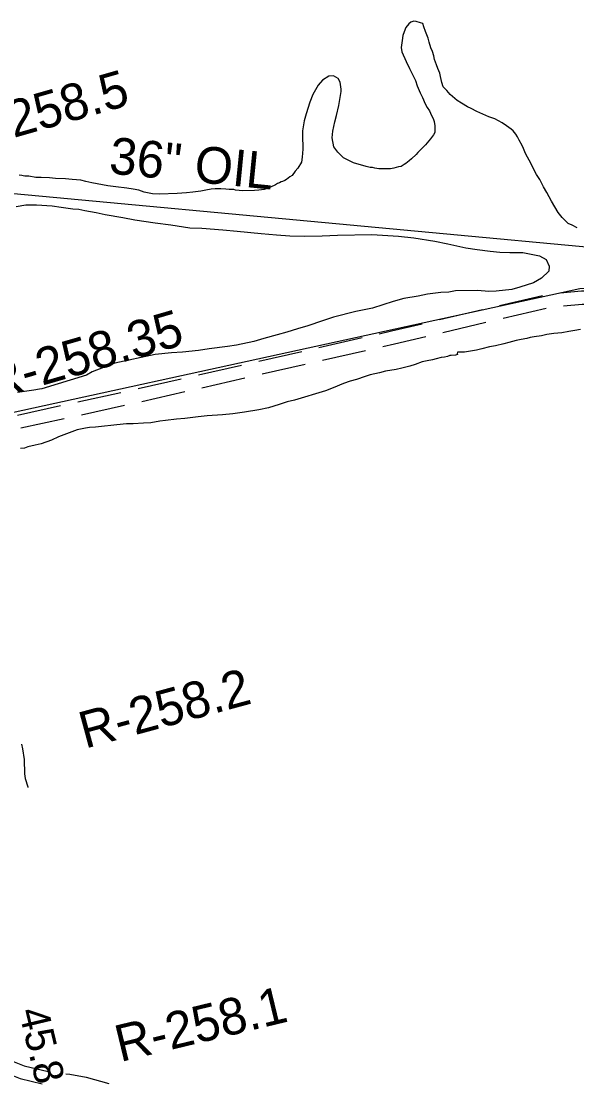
# Model space of a CAD drawing. Extents: x 3250478 to 3288318, y 788638 to 816472.
# Drawn here: x 3279198 to 3280456, y 795832 to 798238 of the extents above; entities that cross this region are included whole.
import ezdxf

# ---------------------------------------------------------------- set-up
doc = ezdxf.new("R2010")
doc.units = 0
for name, color, linetype in [('V-RIVR-RANG', 7, 'Continuous'), ('V-RIVR-RANG-IDEN', 7, 'Continuous'), ('V-ROAD-CNTR', 7, 'Continuous'), ('V-SITE-VEGE', 7, 'Continuous'), ('V-UTIL-IDEN', 7, 'Continuous'), ('V-UTIL-LINE', 7, 'Continuous')]:
    doc.layers.add(name, color=color, linetype=linetype)

msp = doc.modelspace()

# ---------------------------------------------------------------- linework, layer by layer
at = {"layer": 'V-ROAD-CNTR'}
for p, q in [((3280281.4, 797594.3), (3280378.7, 797617.2)), ((3280145.1, 797562.2), (3280242.4, 797585.1)), ((3280289.3, 797565.3), (3280386.6, 797588.2)), ((3280153, 797533.2), (3280250.4, 797556.2)), ((3279872.3, 797499.2), (3279969.8, 797521.4)), ((3279735.8, 797468.1), (3279833.3, 797490.3)), ((3279880.2, 797470.3), (3279977.7, 797492.5)), ((3279599.3, 797437), (3279696.8, 797459.2)), ((3279743.7, 797439.2), (3279841.2, 797461.4)), ((3279462.8, 797405.9), (3279560.3, 797428.1)), ((3279607.2, 797408), (3279704.7, 797430.3)), ((3279326, 797376), (3279423.7, 797397.2)), ((3279470.7, 797376.9), (3279568.2, 797399.2)), ((3279189.2, 797346.2), (3279286.9, 797367.5)), ((3279334, 797347), (3279431.7, 797368.2)), ((3279197.2, 797317.3), (3279294.9, 797338.5))]:
    msp.add_line(p, q, dxfattribs=at)
for points in [[(3280418.3, 797622.6), (3280466.9, 797627.5), (3280518, 797627.1)], [(3280426.3, 797593.3), (3280468.3, 797597.5), (3280526.1, 797597)], [(3280008.8, 797530.3), (3280036.8, 797536.7), (3280106.2, 797553)], [(3280016.7, 797501.4), (3280043.6, 797507.5), (3280114.1, 797524.1)], [(3279198.3, 796600.9), (3279200.6, 796590.6), (3279204.7, 796566), (3279205.2, 796533.4), (3279207.1, 796523.3), (3279212.4, 796503.9), (3279212.8, 796502.5)], [(3279164.1, 795889.3), (3279170.8, 795885.6), (3279204.5, 795872), (3279259.1, 795859.3)], [(3279150.4, 795862.6), (3279157.9, 795858.4), (3279195.4, 795843.3), (3279245.1, 795831.8)], [(3279298.7, 795854.4), (3279307.8, 795853.7), (3279344.8, 795847), (3279396, 795832.5)]]:
    msp.add_lwpolyline(points, dxfattribs=at)
at = {"layer": 'V-SITE-VEGE'}
for p, q in [((3280076.1, 798232.2), (3280068.8, 798223.9)), ((3280080.3, 798236.1), (3280076.1, 798232.2)), ((3280087.3, 798238), (3280080.3, 798236.1)), ((3280092.1, 798237.6), (3280087.3, 798238)), ((3280102.5, 798234.6), (3280092.1, 798237.6)), ((3280107.4, 798232.6), (3280102.5, 798234.6)), ((3280109.8, 798225.1), (3280107.4, 798232.6)), ((3280062.3, 798205.9), (3280060.5, 798194.5)), ((3280067.3, 798220.1), (3280062.3, 798205.9)), ((3280068.8, 798223.9), (3280067.3, 798220.1)), ((3280113.4, 798215), (3280109.8, 798225.1)), ((3280119.7, 798200), (3280113.4, 798215)), ((3280060.5, 798194.5), (3280058.8, 798178.2)), ((3280121.7, 798190.4), (3280119.7, 798200)), ((3280125.8, 798177.5), (3280121.7, 798190.4)), ((3280058.8, 798178.2), (3280060.2, 798168.5)), ((3280060.2, 798168.5), (3280070, 798146.7)), ((3280129.3, 798169.5), (3280125.8, 798177.5)), ((3280132.3, 798159.4), (3280129.3, 798169.5)), ((3280134.2, 798151.3), (3280132.3, 798159.4)), ((3280070, 798146.7), (3280077.5, 798131.2)), ((3280077.5, 798131.2), (3280082.7, 798120.1)), ((3280138.3, 798139.5), (3280134.2, 798151.3)), ((3280141.8, 798131), (3280138.3, 798139.5)), ((3280145.9, 798120.3), (3280141.8, 798131)), ((3279894.9, 798113.9), (3279880.6, 798104.3)), ((3279905.1, 798114.7), (3279894.9, 798113.9)), ((3279915.6, 798108), (3279905.1, 798114.7)), ((3279920.1, 798100.1), (3279915.6, 798108)), ((3280082.7, 798120.1), (3280090.8, 798103.5)), ((3280147.7, 798112.8), (3280145.9, 798120.3)), ((3280150.3, 798099.4), (3280147.7, 798112.8)), ((3279870.7, 798093.2), (3279858.3, 798072.3)), ((3279880.6, 798104.3), (3279870.7, 798093.2)), ((3279922.3, 798083.9), (3279920.1, 798100.1)), ((3279922.4, 798078.5), (3279922.3, 798083.9)), ((3280090.8, 798103.5), (3280094.9, 798091.8)), ((3280094.9, 798091.8), (3280101.3, 798075.8)), ((3280153.9, 798089.2), (3280150.3, 798099.4)), ((3280161.7, 798081.4), (3280153.9, 798089.2)), ((3279858.3, 798072.3), (3279851.3, 798054.8)), ((3279917.4, 798047), (3279922.4, 798078.5)), ((3280101.3, 798075.8), (3280107, 798065.1)), ((3280107, 798065.1), (3280112.9, 798050.7)), ((3280169.5, 798071.9), (3280161.7, 798081.4)), ((3280185, 798058.3), (3280169.5, 798071.9)), ((3279851.3, 798054.8), (3279842.9, 798028.6)), ((3279911.6, 798024.7), (3279917.4, 798047)), ((3280112.9, 798050.7), (3280117.4, 798042.8)), ((3280117.4, 798042.8), (3280122.5, 798034.8)), ((3280122.5, 798034.8), (3280127.2, 798024.7)), ((3280195.5, 798052.7), (3280185, 798058.3)), ((3280208.7, 798044.4), (3280195.5, 798052.7)), ((3280216.9, 798040.3), (3280208.7, 798044.4)), ((3280229.5, 798033.2), (3280216.9, 798040.3)), ((3279839, 798012.8), (3279834.9, 797989.5)), ((3279842.9, 798028.6), (3279839, 798012.8)), ((3279908.3, 798010), (3279911.6, 798024.7)), ((3280127.2, 798024.7), (3280131.1, 798017.8)), ((3280131.1, 798017.8), (3280133, 798010.8)), ((3280133, 798010.8), (3280134.9, 798001.1)), ((3280257.4, 798021.6), (3280229.5, 798033.2)), ((3280270.6, 798016.6), (3280257.4, 798021.6)), ((3280287, 798007.9), (3280270.6, 798016.6)), ((3279834.9, 797989.5), (3279835.3, 797974.9)), ((3279901.8, 797974.2), (3279904, 797988.8)), ((3279904, 797988.8), (3279908.3, 798010)), ((3280135.1, 797995.2), (3280134.8, 797986)), ((3280134.9, 798001.1), (3280135.1, 797995.2)), ((3280297, 798001.1), (3280287, 798007.9)), ((3280308, 797993.9), (3280297, 798001.1)), ((3280311.9, 797989.7), (3280308, 797993.9)), ((3280318, 797982.3), (3280311.9, 797989.7)), ((3279835.3, 797974.9), (3279835.4, 797954.4)), ((3279906.2, 797953.8), (3279901.8, 797974.2)), ((3280120.8, 797967.2), (3280113.5, 797958.4)), ((3280125, 797971.7), (3280120.8, 797967.2)), ((3280131.7, 797980.5), (3280125, 797971.7)), ((3280134.8, 797986), (3280131.7, 797980.5)), ((3280322, 797976), (3280318, 797982.3)), ((3280326, 797968.5), (3280322, 797976)), ((3280332.9, 797956.3), (3280326, 797968.5)), ((3279835.6, 797948.4), (3279834.5, 797930)), ((3279835.4, 797954.4), (3279835.6, 797948.4)), ((3279915.2, 797941.6), (3279906.2, 797953.8)), ((3279928, 797929), (3279915.2, 797941.6)), ((3280096.2, 797940.6), (3280092.5, 797936.1)), ((3280107.2, 797952.2), (3280096.2, 797940.6)), ((3280113.5, 797958.4), (3280107.2, 797952.2)), ((3280335.2, 797949.9), (3280332.9, 797956.3)), ((3280339.9, 797938.7), (3280335.2, 797949.9)), ((3280345, 797930.2), (3280339.9, 797938.7)), ((3279832.6, 797919.2), (3279824.4, 797905.4)), ((3279834.5, 797930), (3279832.6, 797919.2)), ((3279950.5, 797917.3), (3279928, 797929)), ((3279978.8, 797909), (3279950.5, 797917.3)), ((3280069.4, 797916), (3280065.1, 797913.2)), ((3280076.8, 797921.6), (3280069.4, 797916)), ((3280082, 797926.1), (3280076.8, 797921.6)), ((3280092.5, 797936.1), (3280082, 797926.1)), ((3280352.4, 797916.9), (3280345, 797930.2)), ((3280357, 797906.8), (3280352.4, 797916.9)), ((3279818.7, 797898.2), (3279811.4, 797888.8)), ((3279824.4, 797905.4), (3279818.7, 797898.2)), ((3279988.6, 797907.1), (3279978.8, 797909)), ((3279993.5, 797906.7), (3279988.6, 797907.1)), ((3279998.9, 797905.2), (3279993.5, 797906.7)), ((3280008.1, 797903.9), (3279998.9, 797905.2)), ((3280014.6, 797903.5), (3280008.1, 797903.9)), ((3280034.6, 797904.1), (3280014.6, 797903.5)), ((3280041.6, 797904.9), (3280034.6, 797904.1)), ((3280052.3, 797907.9), (3280041.6, 797904.9)), ((3280058.2, 797909.2), (3280052.3, 797907.9)), ((3280065.1, 797913.2), (3280058.2, 797909.2)), ((3280365.1, 797890.8), (3280357, 797906.8)), ((3280372.4, 797879.7), (3280365.1, 797890.8)), ((3279199.3, 797888.9), (3279192.8, 797889.2)), ((3279202.1, 797887.9), (3279199.3, 797888.9)), ((3279205.9, 797887.4), (3279202.1, 797887.9)), ((3279215, 797887.2), (3279205.9, 797887.4)), ((3279230.8, 797884.4), (3279215, 797887.2)), ((3279242.7, 797884.2), (3279230.8, 797884.4)), ((3279262.2, 797883.2), (3279242.7, 797884.2)), ((3279275.7, 797882), (3279262.2, 797883.2)), ((3279298.4, 797881), (3279275.7, 797882)), ((3279313, 797879.8), (3279298.4, 797881)), ((3279333.1, 797877.7), (3279313, 797879.8)), ((3279344, 797874.8), (3279333.1, 797877.7)), ((3279357.6, 797872), (3279344, 797874.8)), ((3279370.1, 797869.7), (3279357.6, 797872)), ((3279394, 797865.5), (3279370.1, 797869.7)), ((3279773.7, 797867.2), (3279762.5, 797862)), ((3279778.5, 797870.5), (3279773.7, 797867.2)), ((3279782.7, 797871.7), (3279778.5, 797870.5)), ((3279786.4, 797874.6), (3279782.7, 797871.7)), ((3279789.7, 797875.2), (3279786.4, 797874.6)), ((3279795, 797877.5), (3279789.7, 797875.2)), ((3279798.7, 797879.8), (3279795, 797877.5)), ((3279806.1, 797885.4), (3279798.7, 797879.8)), ((3279811.4, 797888.8), (3279806.1, 797885.4)), ((3280381, 797863.2), (3280372.4, 797879.7)), ((3279412.4, 797862.8), (3279394, 797865.5)), ((3279436.8, 797859.8), (3279412.4, 797862.8)), ((3279451.5, 797857.5), (3279436.8, 797859.8)), ((3279464.5, 797855.2), (3279451.5, 797857.5)), ((3279476, 797851.2), (3279464.5, 797855.2)), ((3279495, 797846.9), (3279476, 797851.2)), ((3279511.2, 797846.3), (3279495, 797846.9)), ((3279551.2, 797847.5), (3279511.2, 797846.3)), ((3279572.2, 797849.2), (3279551.2, 797847.5)), ((3279586.7, 797850.8), (3279572.2, 797849.2)), ((3279605, 797853.5), (3279586.7, 797850.8)), ((3279615.8, 797855.4), (3279605, 797853.5)), ((3279628.1, 797857.4), (3279615.8, 797855.4)), ((3279637.3, 797858.2), (3279628.1, 797857.4)), ((3279649.7, 797858.6), (3279637.3, 797858.2)), ((3279661.1, 797857.8), (3279649.7, 797858.6)), ((3279668.7, 797857), (3279661.1, 797857.8)), ((3279679.5, 797856.8), (3279668.7, 797857)), ((3279683.3, 797855.8), (3279679.5, 797856.8)), ((3279700.1, 797854.1), (3279683.3, 797855.8)), ((3279726.5, 797854.9), (3279700.1, 797854.1)), ((3279735.7, 797855.8), (3279726.5, 797854.9)), ((3279748.1, 797857.2), (3279735.7, 797855.8)), ((3279755, 797859), (3279748.1, 797857.2)), ((3279762.5, 797862), (3279755, 797859)), ((3280388.4, 797850.5), (3280381, 797863.2)), ((3280399.3, 797830.2), (3280388.4, 797850.5)), ((3280414.1, 797804.8), (3280399.3, 797830.2)), ((3280423.1, 797793.7), (3280414.1, 797804.8)), ((3280437, 797780.1), (3280423.1, 797793.7)), ((3280445.8, 797776), (3280437, 797780.1)), ((3280457.3, 797769.9), (3280445.8, 797776)), ((3280404.2, 797530.5), (3280388.6, 797528.5)), ((3280413.3, 797531.4), (3280404.2, 797530.5)), ((3280422.5, 797532.7), (3280413.3, 797531.4)), ((3280438.1, 797535.3), (3280422.5, 797532.7)), ((3280451.5, 797537.9), (3280438.1, 797535.3)), ((3280464.4, 797539.9), (3280451.5, 797537.9)), ((3280291.4, 797507.2), (3280272.1, 797502.8)), ((3280302.6, 797510.8), (3280291.4, 797507.2)), ((3280319.3, 797515), (3280302.6, 797510.8)), ((3280330, 797517), (3280319.3, 797515)), ((3280342.9, 797519.5), (3280330, 797517)), ((3280351, 797521.4), (3280342.9, 797519.5)), ((3280360.1, 797523.3), (3280351, 797521.4)), ((3280376.7, 797525.9), (3280360.1, 797523.3)), ((3280388.6, 797528.5), (3280376.7, 797525.9)), ((3280181.4, 797481.7), (3280171.7, 797480.9)), ((3280185.7, 797483.5), (3280181.4, 797481.7)), ((3280186.1, 797488.4), (3280185.6, 797485.6)), ((3280185.6, 797485.6), (3280185.7, 797483.5)), ((3280202.3, 797488.8), (3280186.1, 797488.4)), ((3280229.2, 797493.4), (3280202.3, 797488.8)), ((3280241, 797495.9), (3280229.2, 797493.4)), ((3280258.7, 797500.3), (3280241, 797495.9)), ((3280272.1, 797502.8), (3280258.7, 797500.3)), ((3280077.9, 797457), (3280059.7, 797452.2)), ((3280090.2, 797460.6), (3280077.9, 797457)), ((3280105.7, 797466.5), (3280090.2, 797460.6)), ((3280117, 797469), (3280105.7, 797466.5)), ((3280129.3, 797471.5), (3280117, 797469)), ((3280137.9, 797473.4), (3280129.3, 797471.5)), ((3280149.2, 797476.4), (3280137.9, 797473.4)), ((3280156.7, 797477.2), (3280149.2, 797476.4)), ((3280163.7, 797479), (3280156.7, 797477.2)), ((3280169, 797480.8), (3280163.7, 797479)), ((3280171.7, 797480.9), (3280169, 797480.8)), ((3279977, 797433.5), (3279957.3, 797426.9)), ((3279988.3, 797437.1), (3279977, 797433.5)), ((3280009.7, 797442), (3279988.3, 797437.1)), ((3280023.1, 797445.7), (3280009.7, 797442)), ((3280046.8, 797449.6), (3280023.1, 797445.7)), ((3280059.7, 797452.2), (3280046.8, 797449.6)), ((3279927.8, 797417.4), (3279904.4, 797407.5)), ((3279942.8, 797422.7), (3279927.8, 797417.4)), ((3279957.3, 797426.9), (3279942.8, 797422.7)), ((3279887.3, 797401.1), (3279816.6, 797380.1)), ((3279904.4, 797407.5), (3279887.3, 797401.1)), ((3279757.7, 797362.6), (3279736.2, 797358.2)), ((3279781.8, 797370.4), (3279757.7, 797362.6)), ((3279800, 797375.8), (3279781.8, 797370.4)), ((3279816.6, 797380.1), (3279800, 797375.8)), ((3279549.9, 797337), (3279524.6, 797333.5)), ((3279568.3, 797338), (3279549.9, 797337)), ((3279598.4, 797342.2), (3279568.3, 797338)), ((3279618.8, 797344.4), (3279598.4, 797342.2)), ((3279653.4, 797346.5), (3279618.8, 797344.4)), ((3279677.1, 797348.9), (3279653.4, 797346.5)), ((3279703.4, 797352.4), (3279677.1, 797348.9)), ((3279736.2, 797358.2), (3279703.4, 797352.4)), ((3279343.1, 797316.7), (3279324.8, 797312.4)), ((3279352.2, 797318.1), (3279343.1, 797316.7)), ((3279366.2, 797319), (3279352.2, 797318.1)), ((3279373.2, 797319.8), (3279366.2, 797319)), ((3279414.2, 797323.7), (3279373.2, 797319.8)), ((3279436.3, 797326), (3279414.2, 797323.7)), ((3279451.4, 797326.4), (3279436.3, 797326)), ((3279474.6, 797327.7), (3279451.4, 797326.4)), ((3279491.3, 797328.7), (3279474.6, 797327.7)), ((3279511.7, 797332), (3279491.3, 797328.7)), ((3279524.6, 797333.5), (3279511.7, 797332)), ((3279266.1, 797289.6), (3279242.6, 797280.8)), ((3279282.6, 797296.5), (3279266.1, 797289.6)), ((3279324.8, 797312.4), (3279282.6, 797296.5)), ((3279205, 797271.5), (3279196.4, 797270.2)), ((3279213.1, 797273.9), (3279205, 797271.5)), ((3279229.7, 797277.7), (3279213.1, 797273.9)), ((3279242.6, 797280.8), (3279229.7, 797277.7))]:
    msp.add_line(p, q, dxfattribs=at)
for points in [[(3279186, 797818.4), (3279208.6, 797822), (3279232.3, 797822.4), (3279268, 797819.8), (3279288.6, 797816.9), (3279314.6, 797813), (3279328.6, 797812.1), (3279341.7, 797809.1), (3279367.6, 797805.2), (3279388.2, 797800.1), (3279428.3, 797793.2), (3279455.4, 797788.3), (3279500.9, 797781.4), (3279536.6, 797776.6), (3279579.9, 797769.8), (3279606.9, 797769.1), (3279654.5, 797765.6), (3279687, 797762.9), (3279741.1, 797757.3), (3279775.7, 797754.6), (3279806, 797751.8), (3279838.4, 797751.3), (3279879.4, 797751.9), (3279913.9, 797753.6), (3279991.7, 797754.9), (3280052.2, 797751.5), (3280086.8, 797747.8)], [(3280086.8, 797747.8), (3280134.5, 797739.9), (3280163.8, 797733.9), (3280205, 797724.8), (3280230.9, 797720.9), (3280260.2, 797717.1), (3280281.8, 797715.3), (3280304.5, 797714.6), (3280333.7, 797714), (3280371.6, 797707), (3280386.8, 797698.6), (3280393.6, 797683.6), (3280392.7, 797671.7), (3280376.7, 797656.3), (3280358.5, 797645.2), (3280327.4, 797636.1), (3280309.1, 797630.4), (3280273.5, 797626.6), (3280257.3, 797626.3), (3280231.4, 797628.1), (3280181.7, 797627.2), (3280166.6, 797624.8), (3280148.3, 797623.5), (3280118.1, 797619.7), (3280096.6, 797615.1), (3280064.2, 797610.2), (3280040.6, 797603.4), (3279993.3, 797588.5), (3279955.6, 797580.4), (3279905.1, 797567.7), (3279880.4, 797559.7), (3279847.1, 797548.4), (3279823.4, 797541.5), (3279799.8, 797533.6), (3279777.2, 797527.8), (3279747.1, 797519.7), (3279724.5, 797512.9), (3279685.8, 797504.7), (3279665.3, 797501.1), (3279623.3, 797496.1), (3279599.5, 797492.5), (3279562.9, 797488.7), (3279538.1, 797487.2), (3279501.4, 797483.3), (3279409.9, 797463.5), (3279358.4, 797444.3), (3279345.6, 797436.5), (3279244.5, 797405.7), (3279239.1, 797404.5), (3279226.2, 797402.2), (3279220.8, 797402.1), (3279189.6, 797397.3)]]:
    msp.add_lwpolyline(points, dxfattribs=at)
at = {"layer": 'V-UTIL-LINE'}
for points in [[(3274180.3, 796742), (3278434.3, 797696.7), (3279181.3, 797847.9), (3280704.9, 797706.3), (3281577.3, 797678.6)], [(3281615.2, 797623.2), (3280692.5, 797638.3), (3280463.2, 797631.9), (3278519.4, 797207.6), (3274234.6, 796227.9)]]:
    msp.add_lwpolyline(points, dxfattribs=at)

# ---------------------------------------------------------------- texts
at = {"layer": 'V-RIVR-RANG'}
msp.add_text('45.8', height=67, rotation=283.4483, dxfattribs=at).set_placement((3279191.9, 795996.4))
at = {"layer": 'V-RIVR-RANG-IDEN'}
for s, rotation, p in [('R-258.5', 15.9192, (3279067.9, 797941.4)), ('R-258.35', 16.1421, (3279132.2, 797379.8)), ('R-258.2', 15.186, (3279342.4, 796590.4)), ('R-258.1', 13.5854, (3279422.1, 795880.7))]:
    msp.add_text(s, height=83, rotation=rotation, dxfattribs=at).set_placement(p)
at = {"layer": 'V-UTIL-IDEN'}
msp.add_text('36" OIL', height=83, rotation=354.3209, dxfattribs=at).set_placement((3279394.8, 797893.5))

doc.saveas('drawing.dxf')
